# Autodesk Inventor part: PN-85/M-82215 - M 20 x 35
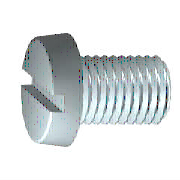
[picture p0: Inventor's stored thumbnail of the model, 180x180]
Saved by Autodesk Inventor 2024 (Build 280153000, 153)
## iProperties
Company: ATC
Created: 2023-03
Part Number: PN-85/M-82215 - M 20 x 35
Material: Stal, miękka
Description: Wkręty z łbem walcowym z rowkiem
Document SubType Name: Modeling
Standard: PN-85/M-82215
Designer: Andrzej Jaskulski
Standards Organization: PN
Language: pl-PL
Size Designation: M 20 x 35
Categories: <MemberInstance><Categories><Category DisplayName="Mocowania" InternalName="e4da775c-781d-43d5-af7c-5136215cf5a6" Mnemonic="FSTN"><Category DisplayName="Śruby"
Density: 7.85 g/cm^3
Appearance: Częściowo polerowany
Checked By: A.J.
Engr Approved By: Andrzej Jaskulski
Mfg Approved By: Andrzej Jaskulski
Authority: A.J.
IsCustomPart: 0
Author: Andrzej Jaskulski
Title: A.J.: Kurs R2024-MEP
Revision Number: 1/24
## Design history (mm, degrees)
sketch "Szkic2"
  geometry: L1 (0, 0)-(0, 14.038) reference; L2 (-15, 2.5)-(15, 2.5); L3 (15, 2.5)-(15, -2.5); L4 (15, -2.5)-(-15, -2.5); L5 (-15, -2.5)-(-15, 2.5); L6 (-15, 0)-(15, 0); L7 (0, 2.5)-(0, -2.5); C1 r 15 at (0, 0) reference; 1 further point
  constraints: 12 end point, 5 midpoint, 2 parallel, 1 collinear, 1 horizontal, 1 perpendicular
  dimensions: "d11" = 5 distance of L4.end L2.start (= SBR); "d12" = 30 distance of L2.start L2.end (= KOD)
extrude "Szczelina" cut sketch "Szkic2" distance "d19" = 5 (= STI); taper "d20" = 0 deg
workplane "Work Plane1"
revolve "Bryła" stored, may be unused: angle "d8" = 90 deg
body "Solid1"
fillet "Zaokrąglenie1" dims "d14" = 0.01 (= RR)
feature "Gwint" dims "d15" = 30 (= GEL), "d16" = 0
chamfer "Faza1" distance "d17" = 1.5335 (= -0.5 x SPD + 0.5 x GD); stored, may be unused: second distance "d18" = 1.53373 (computed from GUL), angle "d36" = 45 deg
sketch "Szkic1"
  geometry: L1 (-11, 0)-(35, 0); L2 (35, 0)-(35, 10); L3 (35, 10)-(5, 10); L4 (5, 10)-(3.466, 9.233); L5 (3.466, 9.233)-(0, 9.233); L6 (0, 9.233)-(0, 15); L7 (-20.2, 0)-(44.2, 0) reference; L8 (0, -3)-(0, 18) reference; L9 (-11, 0)-(-11, 14.038); L10 (0, 15)-(-11, 14.038); L11 (5, 10)-(0, 10)
  constraints: 18 end point, 4 parallel, 2 collinear, 2 perpendicular, 1 horizontal, 1 point on line
  dimensions: "d0" = 35 distance between parallel lines of L2 L6 (= NLG); "d1" = 30 distance from line of L3.end L2 (= GEL); "d2" = 1.53373 horizontal distance of L4.end L3.end (computed from GAL); "d3" = 11 distance from line of L1.start L6 (= KOH); "d4" = 20 diameter of L3 L1 (= GD); "d5" = 18.4665 diameter of L5 L1 (= BDM); "d9" = 30 diameter of L6.end L1 (= KOD); "d10" = 5 deg angle of L10 L1 (= KEWI)
other parameters: "GD" = 20 (= NND) [user parameter; used in 2 equation terms], "NLG" = 35 [user parameter; used in 1 equation term], "GEL" = 30 [user parameter; used in 2 equation terms], "KOD" = 30 [user parameter; used in 2 equation terms], "KOH" = 11 [user parameter; used in 1 equation term], "GAL" = 1.53363 (= 0.61345 x PTC) [user parameter; used in 1 equation term], "SPD" = 16.933 [user parameter; used in 1 equation term], "BDM" = 18.4665 [user parameter; used in 1 equation term], "GUL" = 1.53363 (= 0.61345 x PTC) [user parameter; used in 1 equation term], "RR" = 0.01 [user parameter; used in 1 equation term], "d7" = 0, "SBR" = 5 [user parameter; used in 1 equation term], "STI" = 5 [user parameter; used in 1 equation term], "KEWI" = 5 deg [user parameter; used in 1 equation term], "d37" = 0, "d39" = 0, "PTC" = 2.5 [user parameter; used in 4 equation terms], "TOA" = 30 deg [user parameter], "TPU" = 4 (computed from PTC) [user parameter], "GD1" = 16.93275 (= THREADDIA - 1.2269 x PTC) [user parameter]
